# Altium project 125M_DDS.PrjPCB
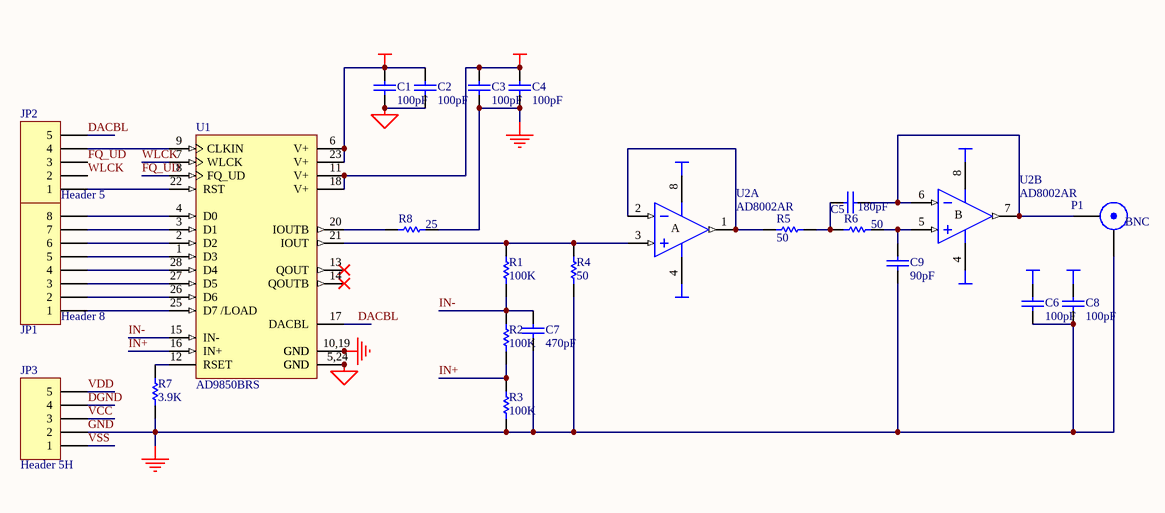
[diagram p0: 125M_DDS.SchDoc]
1 sheet, 23 parts. Net scope: global (net labels, ports and power ports of the same name join across sheets).
Board file: 125M_DDS.PcbDoc

## Sheet 125M_DDS.SchDoc
size A4

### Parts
C1  100pF  [CC2012-0805]
C2  100pF  [CC2012-0805]
C3  100pF  [CC2012-0805]
C4  100pF  [CC2012-0805]
C5  180pF  [CC2012-0805]
C6  100pF  [CC2012-0805]
C7  470pF  [CC2012-0805]
C8  100pF  [CC2012-0805]
C9  90pF  [CC2012-0805]
JP1  Header 8  [HDR1X8]
JP2  Header 5  [HDR1X5]
JP3  Header 5H  [HDR1X5H]
P1  BNC  [BNC_RA CON]
R1  100K  [R2012-0805]
R2  100K  [R2012-0805]
R3  100K  [R2012-0805]
R4  50  [R2012-0805]
R5  50  [R2012-0805]
R6  50  [R2012-0805]
R7  3.9K  [R2012-0805]
R8  25  [R2012-0805]
U1  AD9850BRS  [SSO-G28/E4.3]
U2  AD8002AR  [SO-G8]  (parts A,B of 2)

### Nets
DGND: C1.1 C2.1 JP3.4 U1.5(GND) U1.24(GND)
GND: C3.1 C4.1 C6.1 C7.1 C8.1 C9.1 JP3.2 P1.1(X) R3.1 R4.1 R7.2 R8.2 U1.10(GND) U1.19(GND)
VCC: C3.2 C4.2 C6.2 JP3.3 U1.11(V+) U1.18(V+) U2.8(V+)
VDD: C1.2 C2.2 JP3.5 U1.6(V+) U1.23(V+)
VSS: C8.2 JP3.1 U2.4(V-)
DACBL: JP2.5 U1.17(DACBL)
FQ_UD: JP2.3 U1.8(FQ_UD)
IN+: R2.1 R3.2 U1.16(IN+)
IN-: C7.2 R1.1 R2.2 U1.15(IN-)
WLCK: JP2.2 U1.7(WLCK)
NetC5_1: C5.1 P1.2(Y) U2.6(IN-) U2.7(OUT)
NetC5_2: C5.2 R5.1 R6.2
NetC9_2: C9.2 R6.1 U2.5(IN+)
NetJP1_1: JP1.1 U1.25(D7_/LOAD)
NetJP1_2: JP1.2 U1.26(D6)
NetJP1_3: JP1.3 U1.27(D5)
NetJP1_4: JP1.4 U1.28(D4)
NetJP1_5: JP1.5 U1.1(D3)
NetJP1_6: JP1.6 U1.2(D2)
NetJP1_7: JP1.7 U1.3(D1)
NetJP1_8: JP1.8 U1.4(D0)
NetJP2_1: JP2.1 U1.22(RST)
NetJP2_4: JP2.4 U1.9(CLKIN)
NetR1_2: R1.2 R4.2 U1.21(IOUT) U2.3(IN+)
NetR5_2: R5.2 U2.1(OUT) U2.2(IN-)
NetR7_1: R7.1 U1.12(RSET)
NetR8_1: R8.1 U1.20(IOUTB)

Not connected (* = marked no-connect by the designer): U1 13(QOUT)* 14(QOUTB)*

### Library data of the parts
C1-C9 = Cap: Capacitor; Manufacturer: Generic Components; Class I: Passive
JP1 = Header 8: Header, 8-Pin; Manufacturer: Generic Components; Class I: Connector
JP2 = Header 5: Header, 5-Pin; Manufacturer: Generic Components; Class I: Connector
JP3 = Header 5H: Header, 5-Pin,  Right Angle; Manufacturer: Generic Components; Class I: Connector
P1 = BNC: BNC Elbow Connector; Manufacturer: Generic Components; Class II: RF Coaxial
R1-R8 = Res1: Resistor; Manufacturer: Generic Components; Class I: Passive
U1 = AD9850BRS: CMOS, 125MHz Complete DDS Synthesizer; Manufacturer: Analog Devices; Package Information: Latest Revision: Rev. A 1997; Class I: RF and IF; Class II: Frequency Synthesiser; Note: Pin 17 is unconnected for optimum performance
U2 = AD8002AR: Dual 600MHz, 50mW Current Feedback Amplifier; Manufacturer: Analog Devices; Revision 1: 10-July-2000: SIM Model Added.; Revision 2: July-2002: Re-released for DXP Platform.; Class II: Operational Amplifier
